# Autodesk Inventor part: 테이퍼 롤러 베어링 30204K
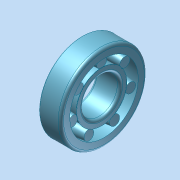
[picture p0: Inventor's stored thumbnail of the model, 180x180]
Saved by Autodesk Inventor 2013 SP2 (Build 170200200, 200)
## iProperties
Created: 2026-01
Part Number: 테이퍼 롤러 베어링 30204K
Material: Generic
Document SubType Name: Modeling
Designer: a
Density: 1 g/cm^3
Author: a
변환 표준: STEP AP214IS
전처리기: Build: 200, Release: 2013 SP2 Update 6 - Date: Thu 07/17/2014
전송 단위: 밀리미터
불확실성: 0.01
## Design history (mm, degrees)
node "테이퍼 롤러 베어링 30204K1"
body "Solid1"
node "Solid1_1"
node "기준1"
node "기준2"
